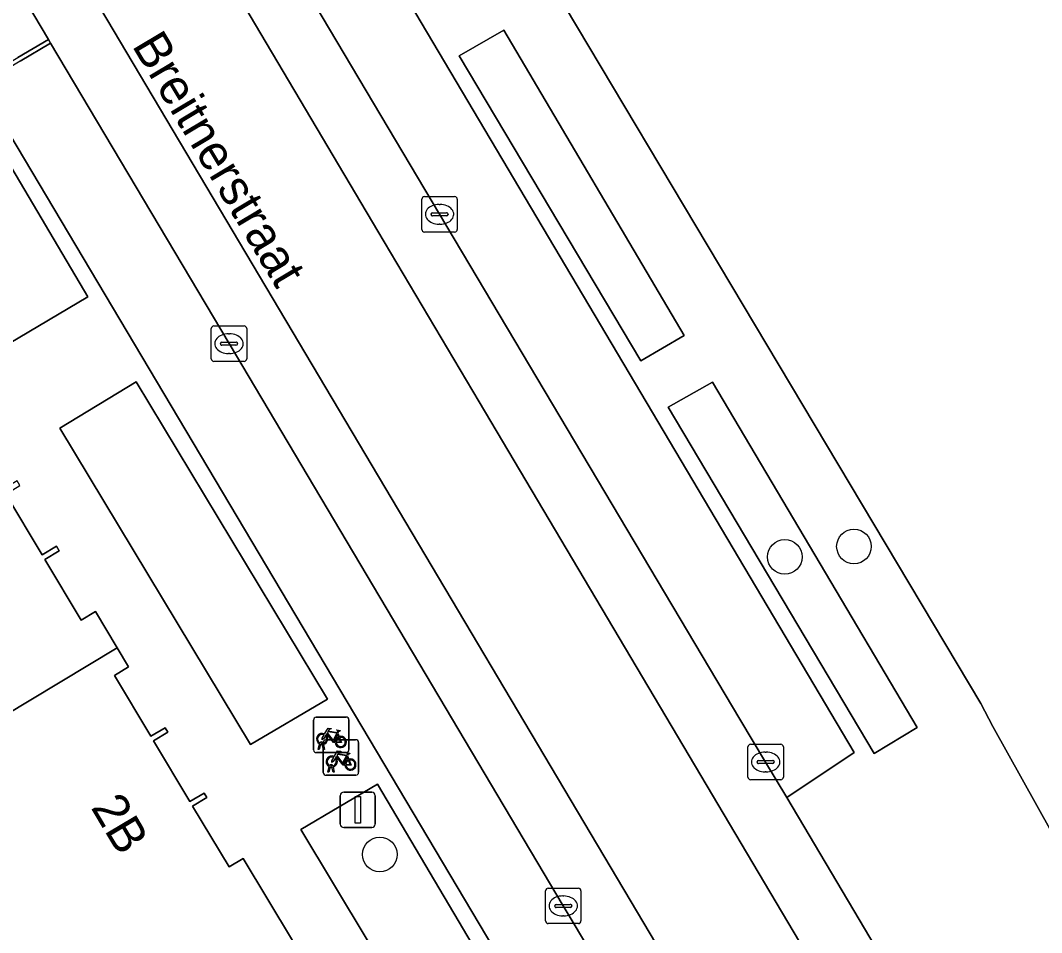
# Model space of a CAD drawing. Extents: x 161771 to 163125, y 382475 to 383179.
# Drawn here: x 162296.6 to 162325.43, y 382923.72 to 382949.47 of the extents above; entities that cross this region are included whole.
import ezdxf

# ---------------------------------------------------------------- set-up
doc = ezdxf.new("R2010")
doc.units = 0
for name, color, linetype in [('IMGEO_Boom', 7, 'Continuous'), ('IMGEO_Erf', 7, 'Continuous'), ('IMGEO_Fietsenrek', 7, 'Continuous'), ('IMGEO_Groenvoorziening', 7, 'Continuous'), ('IMGEO_Kolk', 7, 'Continuous'), ('IMGEO_Lichtmast', 7, 'Continuous'), ('IMGEO_Openbare_ruimte_label', 7, 'Continuous'), ('IMGEO_Pand', 7, 'Continuous'), ('IMGEO_Pand_nummerreeks', 7, 'Continuous'), ('IMGEO_Parkeervlak_open', 7, 'Continuous'), ('IMGEO_Rijbaan_lokaal_gesloten', 7, 'Continuous'), ('IMGEO_Voetpad_open', 7, 'Continuous')]:
    doc.layers.add(name, color=color, linetype=linetype)

msp = doc.modelspace()

# ---------------------------------------------------------------- linework, layer by layer
at = {"layer": 'IMGEO_Boom'}
for centre in [(162320.134, 382934.618), (162318.18, 382934.321), (162306.744, 382925.922)]:
    msp.add_circle(centre, 0.489, dxfattribs=at)
at = {"layer": 'IMGEO_Erf'}
msp.add_lwpolyline([(162282.694, 382998.745), (162285.645, 382993.994), (162299.205, 382971.267), (162304.602, 382962.221), (162323.715, 382930.187), (162324.058, 382929.531), (162333.904, 382911.866), (162340.209, 382901.345), (162341.191, 382899.707), (162342.707, 382897.177), (162347.841, 382889.118), (162350.419, 382884.987), (162352.762, 382884.507), (162396.81, 382874.496)], dxfattribs=at)
at = {"layer": 'IMGEO_Fietsenrek'}
for p, q in [((162304.949, 382929.798), (162305.79, 382929.798)), ((162305.79, 382929.798), (162304.949, 382929.798)), ((162304.874, 382928.873), (162304.874, 382929.714)), ((162304.874, 382929.714), (162304.874, 382928.873)), ((162305.874, 382929.723), (162305.874, 382928.882)), ((162305.874, 382928.882), (162305.874, 382929.723)), ((162305.561, 382929.347), (162305.597, 382929.252)), ((162305.001, 382928.882), (162305.04, 382929.042)), ((162305.07, 382929.03), (162305.035, 382928.882)), ((162305.112, 382929.054), (162305.111, 382929.058)), ((162305.153, 382928.882), (162305.119, 382929.024)), ((162305.143, 382929.065), (162305.144, 382929.058)), ((162305.146, 382928.234), (162305.146, 382929.075)), ((162305.146, 382929.075), (162305.146, 382928.234)), ((162305.151, 382929.028), (162305.186, 382928.882)), ((162305.221, 382929.159), (162306.062, 382929.159)), ((162306.062, 382929.159), (162305.221, 382929.159)), ((162306.146, 382929.084), (162306.146, 382928.243)), ((162306.146, 382928.243), (162306.146, 382929.084)), ((162305.799, 382928.798), (162304.958, 382928.798)), ((162304.958, 382928.798), (162305.799, 382928.798)), ((162305.035, 382928.882), (162305.001, 382928.882)), ((162305.186, 382928.882), (162305.153, 382928.882)), ((162305.833, 382928.708), (162305.869, 382928.613)), ((162305.273, 382928.243), (162305.312, 382928.403)), ((162305.342, 382928.391), (162305.307, 382928.243)), ((162305.384, 382928.415), (162305.383, 382928.419)), ((162305.425, 382928.243), (162305.391, 382928.385)), ((162305.415, 382928.426), (162305.416, 382928.419)), ((162305.423, 382928.389), (162305.458, 382928.243)), ((162306.071, 382928.159), (162305.23, 382928.159)), ((162305.23, 382928.159), (162306.071, 382928.159)), ((162305.307, 382928.243), (162305.273, 382928.243)), ((162305.458, 382928.243), (162305.425, 382928.243))]:
    msp.add_line(p, q, dxfattribs=at)
for points in [[(162305.187, 382929.324), (162305.282, 382929.488), (162305.368, 382929.474), (162305.37, 382929.465), (162305.314, 382929.454), (162305.287, 382929.409), (162305.543, 382929.368)], [(162305.208, 382929.272), (162305.156, 382929.182), (162305.116, 382929.157), (162305.117, 382929.204), (162305.172, 382929.298)], [(162305.483, 382929.08), (162305.433, 382929.08), (162305.242, 382929.331), (162305.223, 382929.299)], [(162305.53, 382929.343), (162305.273, 382929.384), (162305.256, 382929.355), (162305.423, 382929.135), (162305.53, 382929.343)], [(162305.578, 382929.245), (162305.548, 382929.322), (162305.439, 382929.104), (162305.482, 382929.104)], [(162305.512, 382929.104), (162305.632, 382929.103), (162305.588, 382929.217)], [(162305.608, 382929.224), (162305.663, 382929.079), (162305.513, 382929.079)], [(162305.543, 382929.368), (162305.568, 382929.417), (162305.562, 382929.421), (162305.539, 382929.425), (162305.527, 382929.432), (162305.526, 382929.435), (162305.528, 382929.44), (162305.623, 382929.425), (162305.625, 382929.415), (162305.615, 382929.402), (162305.603, 382929.396), (162305.589, 382929.402), (162305.561, 382929.347)], [(162305.48, 382928.633), (162305.428, 382928.543), (162305.388, 382928.518), (162305.389, 382928.565), (162305.444, 382928.659)], [(162305.459, 382928.685), (162305.554, 382928.849), (162305.64, 382928.835), (162305.642, 382928.826), (162305.586, 382928.815), (162305.559, 382928.77), (162305.815, 382928.729)], [(162305.755, 382928.441), (162305.705, 382928.441), (162305.514, 382928.692), (162305.495, 382928.66)], [(162305.802, 382928.704), (162305.545, 382928.745), (162305.528, 382928.716), (162305.695, 382928.496), (162305.802, 382928.704)], [(162305.85, 382928.606), (162305.82, 382928.683), (162305.711, 382928.465), (162305.754, 382928.465)], [(162305.815, 382928.729), (162305.84, 382928.778), (162305.834, 382928.782), (162305.811, 382928.786), (162305.799, 382928.793), (162305.798, 382928.796), (162305.8, 382928.801), (162305.895, 382928.786), (162305.897, 382928.776), (162305.887, 382928.763), (162305.875, 382928.757), (162305.861, 382928.763), (162305.833, 382928.708)], [(162305.784, 382928.465), (162305.904, 382928.464), (162305.86, 382928.578)], [(162305.88, 382928.585), (162305.935, 382928.44), (162305.785, 382928.44)]]:
    msp.add_lwpolyline(points, dxfattribs=at)
for centre, radius, start, end in [((162304.952, 382929.72), 0.0779, 92.4484, 184.2845), ((162304.952, 382929.72), 0.0779, 92.4484, 184.2845), ((162305.796, 382929.72), 0.0779, 2.4484, 94.2845), ((162305.796, 382929.72), 0.0779, 2.4484, 94.2845), ((162305.114, 382929.183), 0.159, 62.6766, 242.1369), ((162305.114, 382929.183), 0.129, 63.3192, 238.903), ((162305.114, 382929.183), 0.129, 283.6043, 43.4302), ((162305.114, 382929.183), 0.159, 283.5766, 46.6042), ((162305.641, 382929.099), 0.159, 113.3408, 178.3217), ((162305.641, 382929.099), 0.159, 187.0065, 105.7708), ((162305.641, 382929.099), 0.129, 113.923, 177.9556), ((162305.641, 382929.099), 0.129, 188.6715, 104.5883), ((162305.094, 382929.054), 0.0499, 12.8025, 158.6934), ((162305.114, 382929.183), 0.159, 253.9967, 271.7867), ((162305.094, 382929.054), 0.0174, 12.8025, 163.4502), ((162305.114, 382929.183), 0.129, 253.415, 269.0204), ((162305.224, 382929.081), 0.0779, 92.4484, 184.2845), ((162305.224, 382929.081), 0.0779, 92.4484, 184.2845), ((162306.068, 382929.081), 0.0779, 2.4484, 94.2845), ((162306.068, 382929.081), 0.0779, 2.4484, 94.2845), ((162304.952, 382928.876), 0.0779, 182.4484, 274.2845), ((162304.952, 382928.876), 0.0779, 182.4484, 274.2845), ((162305.386, 382928.544), 0.159, 62.6766, 242.1369), ((162305.386, 382928.544), 0.129, 63.3192, 238.903), ((162305.386, 382928.544), 0.129, 283.6043, 43.4302), ((162305.386, 382928.544), 0.159, 283.5766, 46.6042), ((162305.913, 382928.46), 0.159, 187.0065, 105.7708), ((162305.796, 382928.876), 0.0779, 272.4484, 4.2845), ((162305.796, 382928.876), 0.0779, 272.4484, 4.2845), ((162305.366, 382928.415), 0.0499, 12.8025, 158.6934), ((162305.386, 382928.544), 0.159, 253.9967, 271.7867), ((162305.366, 382928.415), 0.0174, 12.8025, 163.4502), ((162305.386, 382928.544), 0.129, 253.415, 269.0204), ((162305.913, 382928.46), 0.159, 113.3408, 178.3217), ((162305.913, 382928.46), 0.129, 113.923, 177.9556), ((162305.913, 382928.46), 0.129, 188.6715, 104.5883), ((162305.224, 382928.237), 0.0779, 182.4484, 274.2845), ((162305.224, 382928.237), 0.0779, 182.4484, 274.2845), ((162306.068, 382928.237), 0.0779, 272.4484, 4.2845), ((162306.068, 382928.237), 0.0779, 272.4484, 4.2845)]:
    msp.add_arc(centre, radius, start, end, dxfattribs=at)
at = {"layer": 'IMGEO_Groenvoorziening'}
for points in [[(162295.023, 382947.528), (162296.525, 382948.418), (162297.385, 382948.927), (162295.546, 382952.022), (162294.694, 382951.503), (162293.204, 382950.596), (162290.944, 382949.27), (162296.275, 382940.343), (162298.502, 382941.661)], [(162314.116, 382939.857), (162315.343, 382940.575), (162310.242, 382949.189), (162308.981, 382948.466)], [(162297.705, 382937.959), (162303.091, 382929.024), (162305.264, 382930.304), (162299.863, 382939.26)], [(162320.703, 382928.774), (162321.916, 382929.505), (162316.135, 382939.255), (162314.883, 382938.548)], [(162306.675, 382927.91), (162304.516, 382926.628), (162310.158, 382917.241), (162312.27, 382918.468), (162313.784, 382919.38), (162314.64, 382919.896), (162312.819, 382922.973), (162310.448, 382921.543)]]:
    msp.add_lwpolyline(points, close=True, dxfattribs=at)
at = {"layer": 'IMGEO_Kolk'}
for p, q in [((162308.006, 382944.493), (162308.858, 382944.493)), ((162307.931, 382943.567), (162307.931, 382944.419)), ((162308.419, 382944.273), (162308.444, 382944.273)), ((162308.932, 382944.419), (162308.932, 382943.567)), ((162308.19, 382943.987), (162308.19, 382943.999)), ((162308.628, 382943.95), (162308.23, 382943.95)), ((162308.233, 382944.036), (162308.631, 382944.036)), ((162308.674, 382943.999), (162308.674, 382943.987)), ((162308.442, 382943.713), (162308.417, 382943.713)), ((162308.858, 382943.493), (162308.006, 382943.493)), ((162301.985, 382939.916), (162301.985, 382940.768)), ((162302.06, 382940.842), (162302.912, 382940.842)), ((162302.986, 382940.768), (162302.986, 382939.916)), ((162302.473, 382940.622), (162302.498, 382940.622)), ((162302.244, 382940.336), (162302.244, 382940.348)), ((162302.682, 382940.299), (162302.284, 382940.299)), ((162302.287, 382940.385), (162302.685, 382940.385)), ((162302.728, 382940.348), (162302.728, 382940.336)), ((162302.496, 382940.062), (162302.471, 382940.062)), ((162302.912, 382939.842), (162302.06, 382939.842)), ((162317.139, 382928.106), (162317.139, 382928.958)), ((162317.214, 382929.032), (162318.066, 382929.032)), ((162318.14, 382928.958), (162318.14, 382928.106)), ((162317.627, 382928.812), (162317.652, 382928.812)), ((162317.398, 382928.526), (162317.398, 382928.538)), ((162317.836, 382928.489), (162317.438, 382928.489)), ((162317.441, 382928.575), (162317.839, 382928.575)), ((162317.882, 382928.538), (162317.882, 382928.526)), ((162317.65, 382928.252), (162317.625, 382928.252)), ((162318.066, 382928.032), (162317.214, 382928.032)), ((162311.424, 382924.045), (162311.424, 382924.897)), ((162311.499, 382924.971), (162312.351, 382924.971)), ((162312.425, 382924.897), (162312.425, 382924.045)), ((162311.912, 382924.751), (162311.937, 382924.751)), ((162311.683, 382924.465), (162311.683, 382924.477)), ((162312.121, 382924.428), (162311.723, 382924.428)), ((162311.726, 382924.514), (162312.124, 382924.514)), ((162312.167, 382924.477), (162312.167, 382924.465)), ((162311.935, 382924.191), (162311.91, 382924.191)), ((162312.351, 382923.971), (162311.499, 382923.971))]:
    msp.add_line(p, q, dxfattribs=at)
for points in [[(162308.006, 382944.493), (162308.858, 382944.493)], [(162307.931, 382943.567), (162307.931, 382944.419)], [(162308.932, 382944.419), (162308.932, 382943.567)], [(162308.858, 382943.493), (162308.006, 382943.493)], [(162301.985, 382939.916), (162301.985, 382940.768)], [(162302.06, 382940.842), (162302.912, 382940.842)], [(162302.986, 382940.768), (162302.986, 382939.916)], [(162302.912, 382939.842), (162302.06, 382939.842)], [(162317.139, 382928.106), (162317.139, 382928.958)], [(162317.214, 382929.032), (162318.066, 382929.032)], [(162318.14, 382928.958), (162318.14, 382928.106)], [(162318.066, 382928.032), (162317.214, 382928.032)], [(162311.424, 382924.045), (162311.424, 382924.897)], [(162311.499, 382924.971), (162312.351, 382924.971)], [(162312.425, 382924.897), (162312.425, 382924.045)], [(162312.351, 382923.971), (162311.499, 382923.971)]]:
    msp.add_lwpolyline(points, dxfattribs=at)
for centre, radius, start, end in [((162308.008, 382944.417), 0.0765, 91.552, 178.448), ((162308.008, 382944.417), 0.0765, 91.552, 178.448), ((162308.856, 382944.417), 0.0765, 1.552, 88.448), ((162308.856, 382944.417), 0.0765, 1.552, 88.448), ((162308.23, 382943.996), 0.0403, 85.8775, 175.7526), ((162308.227, 382943.986), 0.0366, 178.938, 274.7102), ((162308.631, 382943.993), 0.043, 264.8664, 352.4533), ((162308.635, 382943.998), 0.0386, 1.7309, 96.639), ((162308.008, 382943.569), 0.0765, 181.552, 268.448), ((162308.008, 382943.569), 0.0765, 181.552, 268.448), ((162308.856, 382943.569), 0.0765, 271.552, 358.448), ((162308.856, 382943.569), 0.0765, 271.552, 358.448), ((162302.062, 382940.766), 0.0765, 91.552, 178.448), ((162302.062, 382940.766), 0.0765, 91.552, 178.448), ((162302.91, 382940.766), 0.0765, 1.552, 88.448), ((162302.91, 382940.766), 0.0765, 1.552, 88.448), ((162302.284, 382940.345), 0.0403, 85.8775, 175.7526), ((162302.281, 382940.335), 0.0366, 178.938, 274.7102), ((162302.685, 382940.342), 0.043, 264.8664, 352.4533), ((162302.689, 382940.347), 0.0386, 1.7309, 96.639), ((162302.062, 382939.918), 0.0765, 181.552, 268.448), ((162302.062, 382939.918), 0.0765, 181.552, 268.448), ((162302.91, 382939.918), 0.0765, 271.552, 358.448), ((162302.91, 382939.918), 0.0765, 271.552, 358.448), ((162317.216, 382928.956), 0.0765, 91.552, 178.448), ((162317.216, 382928.956), 0.0765, 91.552, 178.448), ((162318.064, 382928.956), 0.0765, 1.552, 88.448), ((162318.064, 382928.956), 0.0765, 1.552, 88.448), ((162317.438, 382928.535), 0.0403, 85.8775, 175.7526), ((162317.435, 382928.525), 0.0366, 178.938, 274.7102), ((162317.839, 382928.532), 0.043, 264.8664, 352.4533), ((162317.843, 382928.537), 0.0386, 1.7309, 96.639), ((162317.216, 382928.108), 0.0765, 181.552, 268.448), ((162317.216, 382928.108), 0.0765, 181.552, 268.448), ((162318.064, 382928.108), 0.0765, 271.552, 358.448), ((162318.064, 382928.108), 0.0765, 271.552, 358.448), ((162311.501, 382924.895), 0.0765, 91.552, 178.448), ((162311.501, 382924.895), 0.0765, 91.552, 178.448), ((162312.349, 382924.895), 0.0765, 1.552, 88.448), ((162312.349, 382924.895), 0.0765, 1.552, 88.448), ((162311.723, 382924.474), 0.0403, 85.8775, 175.7526), ((162311.72, 382924.464), 0.0366, 178.938, 274.7102), ((162312.124, 382924.471), 0.043, 264.8664, 352.4533), ((162312.128, 382924.476), 0.0386, 1.7309, 96.639), ((162311.501, 382924.047), 0.0765, 181.552, 268.448), ((162311.501, 382924.047), 0.0765, 181.552, 268.448), ((162312.349, 382924.047), 0.0765, 271.552, 358.448), ((162312.349, 382924.047), 0.0765, 271.552, 358.448)]:
    msp.add_arc(centre, radius, start, end, dxfattribs=at)
for centre, major_axis, ratio, start_param, end_param in [((162308.418, 382943.993), (-0.387, 0.002), 0.722429, 4.712389, 7.853982), ((162308.443, 382943.993), (-0.39, 0.002), 0.717154, 1.570796, 4.712389), ((162302.472, 382940.342), (-0.387, 0.002), 0.722429, 4.712389, 7.853982), ((162302.497, 382940.342), (-0.39, 0.002), 0.717154, 1.570796, 4.712389), ((162317.626, 382928.532), (-0.387, 0.002), 0.722429, 4.712389, 7.853982), ((162317.651, 382928.532), (-0.39, 0.002), 0.717154, 1.570796, 4.712389), ((162311.911, 382924.471), (-0.387, 0.002), 0.722429, 4.712389, 7.853982), ((162311.936, 382924.471), (-0.39, 0.002), 0.717154, 1.570796, 4.712389)]:
    msp.add_ellipse(centre, major_axis=major_axis, ratio=ratio, start_param=start_param, end_param=end_param, dxfattribs=at)
at = {"layer": 'IMGEO_Lichtmast'}
for p, q in [((162305.625, 382926.782), (162305.625, 382927.582)), ((162305.625, 382927.582), (162305.625, 382926.782)), ((162305.725, 382927.682), (162306.515, 382927.682)), ((162306.515, 382927.682), (162305.725, 382927.682)), ((162306.615, 382927.582), (162306.615, 382926.782)), ((162306.615, 382926.782), (162306.615, 382927.582)), ((162306.515, 382926.682), (162305.725, 382926.682)), ((162305.725, 382926.682), (162306.515, 382926.682))]:
    msp.add_line(p, q, dxfattribs=at)
msp.add_lwpolyline([(162306.045, 382927.557), (162306.195, 382927.557), (162306.195, 382926.807), (162306.045, 382926.807), (162306.045, 382927.557)], dxfattribs=at)
for centre, start, end in [((162305.725, 382927.582), 90, 180), ((162305.725, 382927.582), 90, 180), ((162306.515, 382927.582), 0, 90), ((162306.515, 382927.582), 360, 90), ((162305.725, 382926.782), 180, 270), ((162305.725, 382926.782), 180, 270), ((162306.515, 382926.782), 270, 0), ((162306.515, 382926.782), 270, 0)]:
    msp.add_arc(centre, 0.1, start, end, dxfattribs=at)
at = {"layer": 'IMGEO_Pand'}
for points in [[(162297.285, 382934.252), (162297.688, 382934.494), (162297.611, 382934.622), (162297.208, 382934.381), (162296.18, 382936.096), (162296.583, 382936.338), (162296.506, 382936.467), (162296.103, 382936.225), (162295.07, 382937.949), (162295.473, 382938.191), (162294.367, 382940.032), (162287.906, 382936.148), (162292.878, 382927.875), (162299.33, 382931.753), (162298.716, 382932.778), (162298.313, 382932.537)], [(162302.89, 382925.813), (162302.487, 382925.571), (162301.459, 382927.287), (162301.862, 382927.528), (162301.785, 382927.657), (162301.382, 382927.416), (162300.354, 382929.131), (162300.757, 382929.373), (162300.68, 382929.501), (162300.277, 382929.26), (162299.249, 382930.975), (162299.652, 382931.217), (162299.33, 382931.753), (162292.878, 382927.875), (162297.851, 382919.602), (162304.231, 382923.465), (162304.281, 382923.496)]]:
    msp.add_lwpolyline(points, close=True, dxfattribs=at)
at = {"layer": 'IMGEO_Parkeervlak_open'}
for points in [[(162302.215, 382959.014), (162300.224, 382957.807), (162300.77, 382956.887), (162308.432, 382943.993), (162316.912, 382929.741), (162317.64, 382928.532), (162318.235, 382927.528), (162320.137, 382928.801)], [(162302.486, 382940.342), (162297.447, 382948.823), (162296.587, 382948.313), (162295.457, 382947.642), (162310.788, 382921.877), (162311.9, 382922.562), (162312.752, 382923.086), (162311.925, 382924.471)]]:
    msp.add_lwpolyline(points, close=True, dxfattribs=at)
at = {"layer": 'IMGEO_Rijbaan_lokaal_gesloten'}
for points in [[(162252.687, 383027.32), (162258.27, 383017.942), (162277.114, 382986.385), (162314.204, 382923.986), (162330.304, 382896.843), (162338.934, 382882.25), (162339.793, 382880.803)], [(162341.807, 382884.166), (162340.693, 382886.098), (162333.368, 382898.598), (162322.883, 382916.238), (162309.554, 382938.696), (162306.687, 382943.516), (162275.079, 382996.8)], [(162275.079, 382996.8), (162306.687, 382943.516), (162309.554, 382938.696), (162322.883, 382916.238), (162333.368, 382898.598), (162340.693, 382886.098), (162341.807, 382884.166)], [(162344.002, 382884.116), (162343.193, 382885.422), (162339.727, 382891.336), (162335.002, 382899.266), (162326.603, 382913.414), (162324.516, 382916.948), (162318.235, 382927.528), (162317.64, 382928.532), (162316.912, 382929.741), (162308.432, 382943.993), (162300.77, 382956.887), (162300.224, 382957.807), (162293.232, 382969.581), (162288.514, 382977.525), (162281.441, 382989.446), (162278.279, 382994.741), (162277.713, 382995.702)], [(162339.793, 382880.803), (162338.934, 382882.25), (162330.304, 382896.843), (162314.204, 382923.986), (162277.114, 382986.385)], [(162295.546, 382952.022), (162297.385, 382948.927), (162297.447, 382948.823), (162302.486, 382940.342), (162311.925, 382924.471), (162312.752, 382923.086), (162312.819, 382922.973), (162314.64, 382919.896), (162317.99, 382914.237), (162320.653, 382909.74), (162327.107, 382898.845), (162329.048, 382895.587), (162330.45, 382893.21), (162336.215, 382883.528), (162338.393, 382879.852)]]:
    msp.add_lwpolyline(points, dxfattribs=at)
at = {"layer": 'IMGEO_Voetpad_open'}
for points in [[(162298.198, 382970.688), (162299.205, 382971.267), (162285.645, 382993.994), (162282.694, 382998.745), (162282.561, 382998.663), (162282.621, 382998.564), (162281.332, 382997.822), (162277.713, 382995.702), (162278.279, 382994.741), (162281.441, 382989.446), (162283.412, 382990.65), (162295.219, 382970.753), (162293.232, 382969.581), (162300.224, 382957.807), (162302.215, 382959.014), (162320.137, 382928.801), (162318.235, 382927.528), (162324.516, 382916.948), (162326.472, 382918.127), (162341.708, 382892.457), (162339.727, 382891.336), (162343.193, 382885.422), (162344.002, 382884.116)], [(162350.419, 382884.987), (162347.841, 382889.118), (162342.707, 382897.177), (162341.191, 382899.707), (162340.209, 382901.345), (162333.904, 382911.866), (162324.058, 382929.531), (162323.715, 382930.187), (162304.602, 382962.221), (162303.031, 382961.271)], [(162296.587, 382948.313), (162297.447, 382948.823), (162297.385, 382948.927), (162296.525, 382948.418)], [(162295.023, 382947.528), (162298.502, 382941.661), (162296.275, 382940.343)], [(162329.048, 382895.587), (162327.107, 382898.845), (162325.106, 382897.667), (162316.009, 382913.063), (162317.13, 382913.727), (162313.784, 382919.38), (162312.27, 382918.468), (162310.158, 382917.241), (162304.516, 382926.628), (162306.675, 382927.91), (162310.448, 382921.543), (162312.819, 382922.973), (162312.752, 382923.086), (162311.9, 382922.562), (162310.788, 382921.877), (162295.457, 382947.642)], [(162296.18, 382936.096), (162297.208, 382934.381), (162297.611, 382934.622), (162297.688, 382934.494), (162297.285, 382934.252), (162298.313, 382932.537), (162298.716, 382932.778), (162299.33, 382931.753), (162299.652, 382931.217), (162299.249, 382930.975), (162300.277, 382929.26), (162300.68, 382929.501), (162300.757, 382929.373), (162300.354, 382929.131), (162301.382, 382927.416), (162301.785, 382927.657), (162301.862, 382927.528), (162301.459, 382927.287), (162302.487, 382925.571), (162302.89, 382925.813), (162304.281, 382923.496)]]:
    msp.add_lwpolyline(points, dxfattribs=at)
for points in [[(162308.981, 382948.466), (162310.242, 382949.189), (162315.343, 382940.575), (162314.116, 382939.857)], [(162303.091, 382929.024), (162297.705, 382937.959), (162299.863, 382939.26), (162305.264, 382930.304)], [(162320.703, 382928.774), (162314.883, 382938.548), (162316.135, 382939.255), (162321.916, 382929.505)]]:
    msp.add_lwpolyline(points, close=True, dxfattribs=at)

# ---------------------------------------------------------------- texts
at = {"layer": 'IMGEO_Openbare_ruimte_label'}
msp.add_text('Breitnerstraat', height=1, rotation=300.7967, dxfattribs=at).set_placement((162299.731, 382948.757))
at = {"layer": 'IMGEO_Pand_nummerreeks'}
msp.add_text('2B', height=1, rotation=300.739, dxfattribs=at).set_placement((162298.57, 382927.25))

doc.saveas('drawing.dxf')
